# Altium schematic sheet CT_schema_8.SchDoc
size 278 x 170 mm
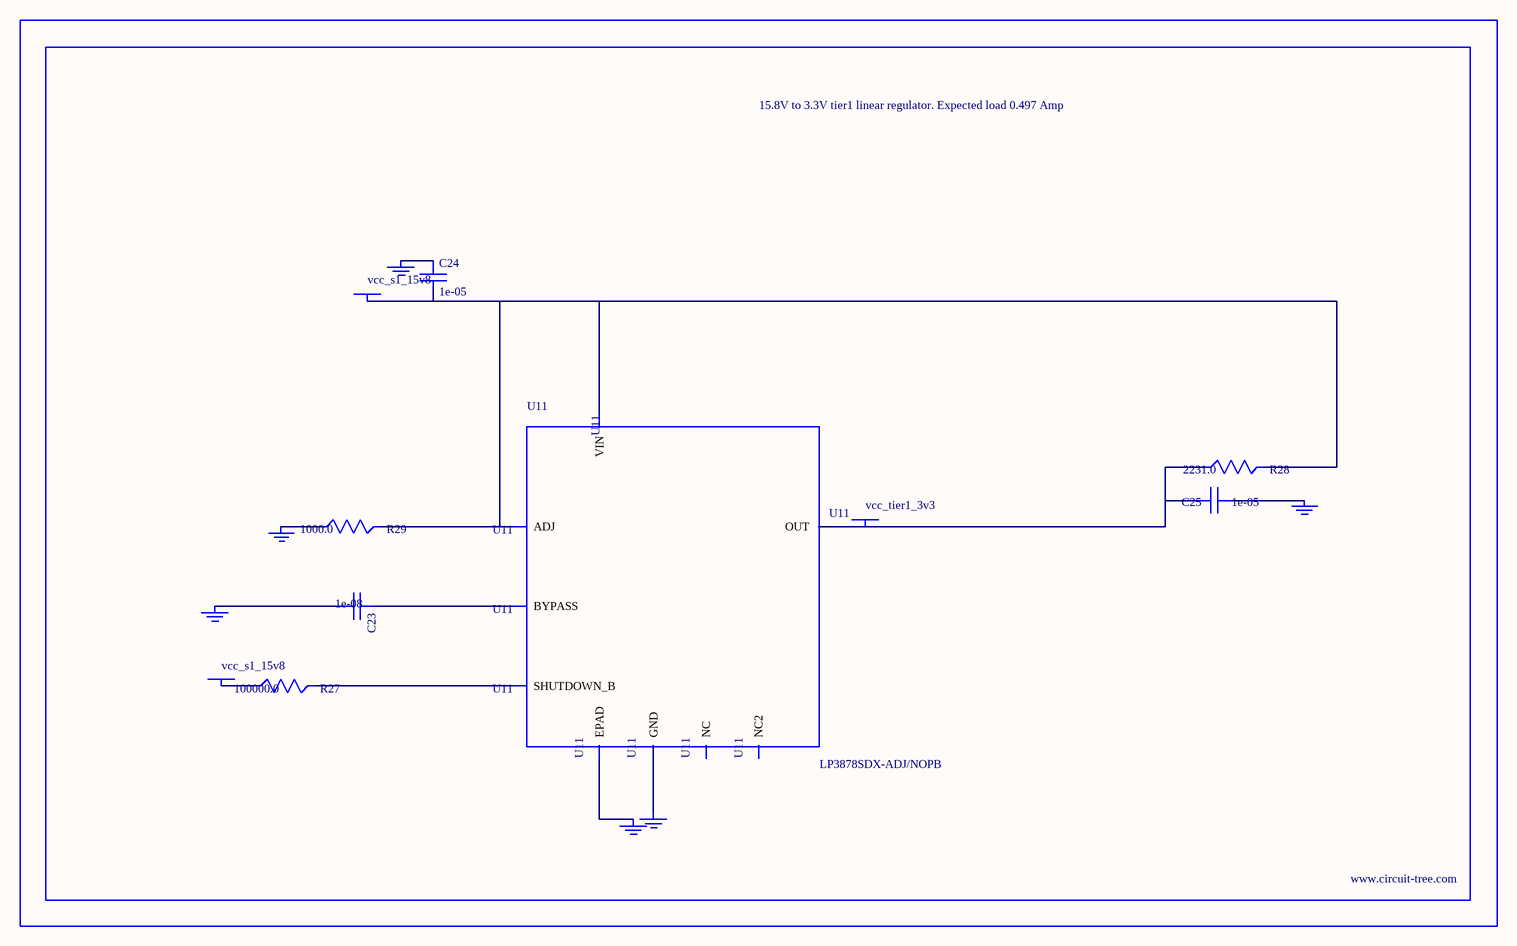
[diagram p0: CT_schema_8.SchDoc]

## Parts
BORDER7  (no value)
C23  1e-08  [C0402]
C24  1e-05  [C1210]
C25  1e-05  [C1210]
GND_INSTANCE_7_0  (no value)
GND_INSTANCE_7_1  (no value)
GND_INSTANCE_7_2  (no value)
GND_INSTANCE_7_3  (no value)
GND_INSTANCE_7_4  (no value)
GND_INSTANCE_7_5  (no value)
POWER_INSTANCE_7_0  vcc_s1_15v8
POWER_INSTANCE_7_1  vcc_s1_15v8
POWER_INSTANCE_7_2  vcc_tier1_3v3
R27  100000.0  [R0603]
R28  2231.0  [R0603]
R29  1000.0  [R0603]
U11  LP3878SDX-ADJ/NOPB  [WSON-8]

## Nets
NetC23_1: C23.1 U11.1(BYPASS)
NetC23_2: C23.2 GND_INSTANCE_7_0.0(GND)
NetC24_1: C24.1 GND_INSTANCE_7_1.0(GND)
NetC24_2: C24.2 POWER_INSTANCE_7_0.0(PWR) R28.2 R29.2 U11.4(VIN) U11.6(ADJ)
NetC25_1: C25.1 GND_INSTANCE_7_2.0(GND)
NetC25_2: C25.2 POWER_INSTANCE_7_2.0(PWR) R28.1 U11.5(OUT)
NetGND_INSTANCE_7_3_0: GND_INSTANCE_7_3.0(GND) R29.1
NetGND_INSTANCE_7_4_0: GND_INSTANCE_7_4.0(GND) U11.PAD(EPAD)
NetGND_INSTANCE_7_5_0: GND_INSTANCE_7_5.0(GND) U11.3(GND)
NetPOWER_INSTANCE_7_1_0: POWER_INSTANCE_7_1.0(PWR) R27.1
NetR27_2: R27.2 U11.8(SHUTDOWN_B)

Not connected (* = marked no-connect by the designer): U11 2(NC) 7(NC2)

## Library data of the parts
BORDER7 = BORDER_PAGE7
C23 = C0402C103K3RAC
C24 = C1210C106K5PACTU
C25 = GRM32DR61E106MA12L
GND_INSTANCE_7_0-GND_INSTANCE_7_5 = GND
POWER_INSTANCE_7_0-POWER_INSTANCE_7_2 = PWR
R27 = RC0603JR-07100KL
R28 = R28
R29 = RC0603JR-071KL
